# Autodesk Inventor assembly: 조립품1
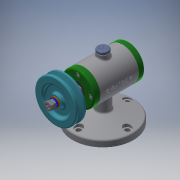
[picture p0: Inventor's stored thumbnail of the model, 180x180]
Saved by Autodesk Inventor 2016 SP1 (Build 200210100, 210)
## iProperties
Created: 2018-12
Part Number: 조립품1
Material: 일반
Document SubType Name: Assembly
Designer: basic
Author: basic
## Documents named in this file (15)
- C:\Users\basic\Desktop\481208V1021\481208V1021\조립품1.iam
- C:\Users\basic\Desktop\481208V1021\481208V1021\부품1.ipt
- C:\Users\basic\Desktop\481208V1021\481208V1021\베어링 15 x 32 x 9.ipt
- C:\Users\basic\Desktop\481208V1021\481208V1021\축.ipt
- C:\Users\basic\Desktop\481208V1021\481208V1021\앞커버.ipt
- C:\Users\basic\Desktop\481208V1021\481208V1021\뒤커버.ipt
- C:\Users\basic\Desktop\481208V1021\481208V1021\오일 실 15 25 7.ipt
- C:\Users\basic\Desktop\481208V1021\481208V1021\볼트 M4 x 12.ipt
- C:\Users\basic\Desktop\481208V1021\481208V1021\고무캡.ipt
- C:\Users\basic\Desktop\481208V1021\481208V1021\V벨트풀리.ipt
- C:\Users\basic\Desktop\481208V1021\481208V1021\키 3 x 3 x 12.ipt
- C:\Users\basic\Desktop\481208V1021\481208V1021\와셔 8x17.ipt
- C:\Users\basic\Desktop\481208V1021\481208V1021\스프링와셔 8.ipt
- C:\Users\basic\Desktop\481208V1021\481208V1021\너트 M8.ipt
- 너트 M8.ipt
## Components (2 placed, 2 different names)
1. 고무캡:1
2. V벨트풀리:1
